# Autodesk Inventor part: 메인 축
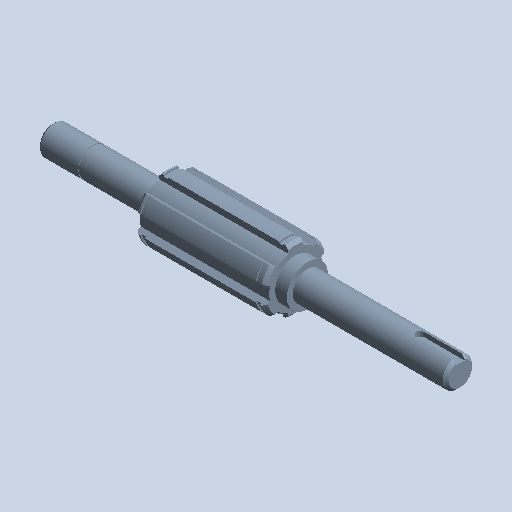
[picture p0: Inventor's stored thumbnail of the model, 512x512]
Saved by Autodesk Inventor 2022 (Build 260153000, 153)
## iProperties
Created: 2021-07
Part Number: 메인 축
Document SubType Name: 모델링
Designer: mdu
Mass: 168.566 g
Surface Area: 72.5104 cm^2
Volume: 21.4461 cm^3
Density: 7.86 g/cm^3
Material: 강철, 연강
Appearance: 연한 강청색
변환 표준: STEP AP214IS
파일 이름: C:\Users\SeoGD\Desktop\?쒗뿕\硫붿씤 異?.stp
전처리기: Build: 253, Release: 2010 SP1 - Date: Wed 07/29/2009
전송 단위: 밀리미터
불확실성: 0.01
Author: mdu
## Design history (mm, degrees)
sketch "스케치1"
  geometry: L1 (-69.5, 0)-(69.5, 0); L2 (69.5, 0)-(69.5, 5); L3 (69.5, 5)-(55.5, 5); L4 (55.5, 5)-(55.5, 4.8); L5 (55.5, 4.8)-(54.35, 4.8); L6 (54.35, 4.8)-(54.35, 5); L7 (54.35, 5)-(30.5, 5); L8 (30.5, 5)-(30.5, 9); L9 (30.5, 9)-(-13.5, 9); L10 (-13.5, 9)-(-13.5, 7); L11 (-13.5, 7)-(-17.5, 7); L12 (-17.5, 7)-(-17.5, 5); L13 (-17.5, 5)-(-69.5, 5); L14 (-69.5, 5)-(-69.5, 0); 2 further points
  constraints: 28 end point, 9 parallel, 4 collinear, 2 perpendicular, 1 coincident, 1 horizontal, 1 midpoint
  dimensions: "d2" = 1.15 distance between parallel lines of L6 L4; "d3" = 10 diameter of L3 L1; "d4" = 9.6 diameter of L5 L1; "d6" = 44 distance between parallel lines of L10 L8; "d7" = 4 distance between parallel lines of L12 L10; "d8" = 14 diameter of L11 L1; "d9" = 18 diameter of L9 L1; "d33" = 52 distance from line of L12.end L14; "d37" = 39 distance between parallel lines of L8 L2; "d38" = 14 distance between parallel lines of L2 L4
revolve "회전1" sketch "스케치1" stored, may be unused: angle "d10" = 90 deg
sketch "스케치2"
  geometry: L1 (2.5, 10.712)-(2.5, 8.646); L2 (-2.5, 10.712)-(-2.5, 8.646); A1 r 9 centre (0, 0) between (2.5, 8.646) and (-2.5, 8.646) reference; A2 r 11 centre (0, 0) between (2.5, 10.712) and (-2.5, 10.712); 1 further point
  constraints: 4 end point, 4 point on circle, 2 parallel, 1 centre point, 1 coincident, 1 vertical
  dimensions: "d11" = 22 diameter of A2; "d12" = 5 distance between parallel lines of L1 L2
extrude "돌출1" join sketch "스케치2" stored distance "d13" = 10; taper "d14" = 0 deg
chamfer "모따기1" distance "d15" = 1; stored, may be unused: second distance "d16" = 2, angle "d17" = 45 deg
node "작업 평면1"
node "작업 평면2"
sketch "스케치3"
  geometry: L1 (2.5, 10.712)-(2.5, 10.198); L2 (-2.5, 10.712)-(-2.5, 10.198); A1 r 11 centre (0, 0) between (2.5, 10.712) and (-2.5, 10.712) reference; A2 r 10.5 centre (0, 0) between (2.5, 10.198) and (-2.5, 10.198); 1 further point
  constraints: 4 end point, 2 point on circle, 1 centre point, 1 coincident, 1 parallel, 1 vertical
  dimensions: "d19" = 21 diameter of A2
extrude "돌출2" cut sketch "스케치3" distance "d20" = 1.35; taper "d21" = 0 deg
node "작업 평면3"
sketch "스케치4"
  geometry: L1 (-26, -5)-(-26, 5) reference; L2 (-26, 1.5)-(-12.5, 1.5); L3 (-12.5, -1.5)-(-26, -1.5); A1 r 1.5 centre (-12.5, 0) between (-12.5, -1.5) and (-12.5, 1.5); 2 further points
  constraints: 4 end point, 2 perpendicular, 2 point on circle, 2 point on line, 2 tangent, 1 centre point, 1 horizontal alignment, 1 midpoint
  dimensions: "d25" = 3 distance between parallel lines of L3 L2; "d26" = 15 dimension on A1 L1
extrude "돌출3" cut sketch "스케치4" distance "d27" = 1.8; taper "d28" = 0 deg
chamfer "모따기2" distance "d29" = 1; stored, may be unused: second distance "d30" = 2, angle "d31" = 45 deg
node "솔리드1"
node "솔리드 본체"
node "곡면 본체"
mirror "대칭1"
pattern_circular "원형 패턴1" dims "d23" = 360 deg
node "솔리드2"
other parameters: "d18" = -1.65
